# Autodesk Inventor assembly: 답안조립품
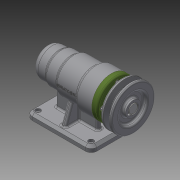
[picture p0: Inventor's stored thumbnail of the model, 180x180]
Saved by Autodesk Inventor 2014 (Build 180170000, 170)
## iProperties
Created: 2016-06
Part Number: 답안조립품
Document SubType Name: Assembly
Designer: SEC
Author: SEC
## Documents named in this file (12)
- C:\Documents and Settings\SEC\바탕 화면\460607V1007\답안조립품.iam
- C:\Documents and Settings\SEC\바탕 화면\460607V1007\본체.ipt
- C:\Documents and Settings\SEC\바탕 화면\460607V1007\커버.ipt
- C:\Documents and Settings\SEC\바탕 화면\460607V1007\베어링 51202.ipt
- C:\Documents and Settings\SEC\바탕 화면\460607V1007\베어링 6004.ipt
- C:\Documents and Settings\SEC\바탕 화면\460607V1007\어댑터슬리브.ipt
- C:\Documents and Settings\SEC\바탕 화면\460607V1007\볼트 M4 x 12.ipt
- C:\Documents and Settings\SEC\바탕 화면\460607V1007\축.ipt
- C:\Documents and Settings\SEC\바탕 화면\460607V1007\키 5 x 5 x 16.ipt
- C:\Documents and Settings\SEC\바탕 화면\460607V1007\V벨트풀리.ipt
- C:\Documents and Settings\SEC\바탕 화면\460607V1007\멈춤나사 M3x8.ipt
- C:\Documents and Settings\SEC\바탕 화면\460607V1007\오일 실.ipt
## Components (6 placed, 2 different names)
1. ISO 4762 M4 x 12:1 — 각도:1
2. V벨트풀리:1 — 각도:3
3. ISO 4762 M4 x 12:2 — 각도:5
4. ISO 4762 M4 x 12:3
5. ISO 4762 M4 x 12:4
6. ISO 4762 M4 x 12:5
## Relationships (3: Angle 3)
- 각도:1 [Angle]: ISO 4762 M4 x 12:1
- 각도:3 [Angle]: V벨트풀리:1
- 각도:5 [Angle]: ISO 4762 M4 x 12:2
